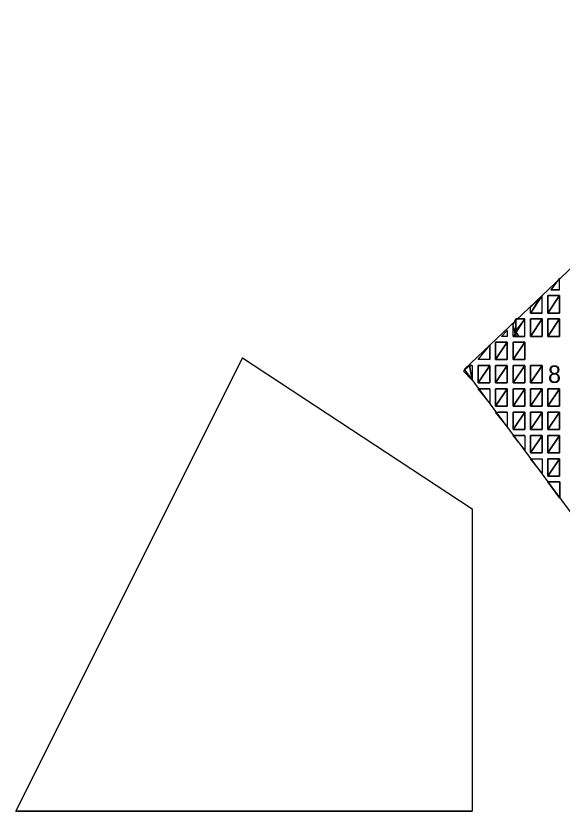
# Model space of a CAD drawing. Extents: x 0 to 34, y -1.2 to 22.
# Drawn here: x 2.909 to 3.443, y 4.123 to 4.9 of the extents above; entities that cross this region are included whole.
import ezdxf

# ---------------------------------------------------------------- set-up
doc = ezdxf.new("R2010")
doc.units = 0
doc.layers.add('Default', color=7, linetype='Continuous')

msp = doc.modelspace()

# ---------------------------------------------------------------- linework, layer by layer
at = {"layer": 'Default'}
for p, q in [((3.71021, 4.89963), (3.34713, 4.55419)), ((3.44033, 4.63213), (3.44033, 4.64351)), ((3.44033, 4.63213), (3.43179, 4.63213)), ((3.42326, 4.60937), (3.42326, 4.62644)), ((3.42895, 4.62644), (3.42895, 4.60937)), ((3.44033, 4.62644), (3.42895, 4.62644)), ((3.44033, 4.60937), (3.44033, 4.62644)), ((3.41188, 4.60937), (3.41188, 4.61506)), ((3.42326, 4.60937), (3.41188, 4.60937)), ((3.42895, 4.60937), (3.44033, 4.60937)), ((3.40619, 4.60368), (3.39765, 4.60368)), ((3.40619, 4.58661), (3.40619, 4.60368)), ((3.41188, 4.60368), (3.41188, 4.58661)), ((3.42326, 4.60368), (3.41188, 4.60368)), ((3.42326, 4.58661), (3.42326, 4.60368)), ((3.44033, 4.60368), (3.42895, 4.60368)), ((3.42895, 4.60368), (3.42895, 4.58661)), ((3.44033, 4.58661), (3.44033, 4.60368)), ((3.39481, 4.58661), (3.39481, 4.59799)), ((3.38912, 4.58661), (3.38342, 4.58661)), ((3.40619, 4.58661), (3.39481, 4.58661)), ((3.41188, 4.58661), (3.42326, 4.58661)), ((3.42895, 4.58661), (3.44033, 4.58661)), ((3.38912, 4.58092), (3.37773, 4.58092)), ((3.37773, 4.58092), (3.37773, 4.56385)), ((3.38912, 4.56385), (3.38912, 4.58092)), ((3.40619, 4.58092), (3.39481, 4.58092)), ((3.39481, 4.58092), (3.39481, 4.56385)), ((3.40619, 4.56385), (3.40619, 4.58092)), ((3.37204, 4.56385), (3.37204, 4.57523)), ((3.1305, 4.56547), (2.90919, 4.12284)), ((3.1305, 4.56547), (3.35479, 4.41798)), ((3.37204, 4.56385), (3.36066, 4.56385)), ((3.37773, 4.56385), (3.38912, 4.56385)), ((3.39481, 4.56385), (3.40619, 4.56385)), ((3.34772, 4.55371), (3.50785, 4.3379)), ((3.35497, 4.55816), (3.35213, 4.55816)), ((3.35497, 4.55816), (3.35497, 4.54393)), ((3.37204, 4.55816), (3.36066, 4.55816)), ((3.36066, 4.55816), (3.36066, 4.54109)), ((3.37204, 4.54109), (3.37204, 4.55816)), ((3.37773, 4.55816), (3.37773, 4.54109)), ((3.38912, 4.55816), (3.37773, 4.55816)), ((3.38912, 4.54109), (3.38912, 4.55816)), ((3.40619, 4.55816), (3.39481, 4.55816)), ((3.39481, 4.55816), (3.39481, 4.54109)), ((3.40619, 4.54109), (3.40619, 4.55816)), ((3.41188, 4.55816), (3.41188, 4.54109)), ((3.42326, 4.55816), (3.41188, 4.55816)), ((3.42326, 4.54109), (3.42326, 4.55816)), ((3.36066, 4.54109), (3.37204, 4.54109)), ((3.37773, 4.54109), (3.38912, 4.54109)), ((3.39481, 4.54109), (3.40619, 4.54109)), ((3.41188, 4.54109), (3.42326, 4.54109)), ((3.37204, 4.53539), (3.36066, 4.53539)), ((3.37204, 4.53539), (3.37204, 4.52117)), ((3.38912, 4.53539), (3.37773, 4.53539)), ((3.37773, 4.53539), (3.37773, 4.51832)), ((3.38912, 4.51832), (3.38912, 4.53539)), ((3.40619, 4.53539), (3.39481, 4.53539)), ((3.39481, 4.53539), (3.39481, 4.51832)), ((3.40619, 4.51832), (3.40619, 4.53539)), ((3.41188, 4.53539), (3.41188, 4.51832)), ((3.42326, 4.53539), (3.41188, 4.53539)), ((3.42326, 4.51832), (3.42326, 4.53539)), ((3.44033, 4.53539), (3.42895, 4.53539)), ((3.42895, 4.53539), (3.42895, 4.51832)), ((3.44033, 4.51832), (3.44033, 4.53539)), ((3.37773, 4.51832), (3.38912, 4.51832)), ((3.39481, 4.51832), (3.40619, 4.51832)), ((3.41188, 4.51832), (3.42326, 4.51832)), ((3.42895, 4.51832), (3.44033, 4.51832)), ((3.38912, 4.51263), (3.38058, 4.51263)), ((3.38912, 4.51263), (3.38912, 4.49841)), ((3.40619, 4.51263), (3.39481, 4.51263)), ((3.39481, 4.51263), (3.39481, 4.49556)), ((3.40619, 4.49556), (3.40619, 4.51263)), ((3.42326, 4.51263), (3.41188, 4.51263)), ((3.41188, 4.51263), (3.41188, 4.49556)), ((3.42326, 4.49556), (3.42326, 4.51263)), ((3.42895, 4.51263), (3.42895, 4.49556)), ((3.44033, 4.51263), (3.42895, 4.51263)), ((3.44033, 4.49556), (3.44033, 4.51263)), ((3.39481, 4.49556), (3.40619, 4.49556)), ((3.40619, 4.48987), (3.39481, 4.48987)), ((3.40619, 4.48987), (3.40619, 4.47565)), ((3.41188, 4.49556), (3.42326, 4.49556)), ((3.42326, 4.48987), (3.41188, 4.48987)), ((3.41188, 4.48987), (3.41188, 4.4728)), ((3.42326, 4.4728), (3.42326, 4.48987)), ((3.42895, 4.49556), (3.44033, 4.49556)), ((3.42895, 4.48987), (3.42895, 4.4728)), ((3.44033, 4.48987), (3.42895, 4.48987)), ((3.44033, 4.4728), (3.44033, 4.48987)), ((3.41188, 4.4728), (3.42326, 4.4728)), ((3.41188, 4.46711), (3.42326, 4.46711)), ((3.42326, 4.46711), (3.42326, 4.45288)), ((3.42895, 4.4728), (3.44033, 4.4728)), ((3.44033, 4.46711), (3.42895, 4.46711)), ((3.42895, 4.46711), (3.42895, 4.45004)), ((3.44033, 4.45004), (3.44033, 4.46711)), ((3.44033, 4.44435), (3.4288, 4.44435)), ((3.42895, 4.45004), (3.44033, 4.45004)), ((3.44033, 4.44435), (3.44033, 4.429)), ((3.35479, 4.41798), (3.35479, 4.12284)), ((2.90919, 4.12284), (3.35479, 4.12284))]:
    msp.add_line(p, q, dxfattribs=at)
for points in [[(3.43179, 4.63213), (3.44033, 4.63213), (3.44033, 4.64351)], [(3.41188, 4.60937), (3.42326, 4.60937), (3.42326, 4.62644)], [(3.41188, 4.60937), (3.41188, 4.61506), (3.42041, 4.6236)], [(3.42895, 4.60937), (3.42895, 4.62644), (3.44033, 4.62644)], [(3.44033, 4.62644), (3.44033, 4.60937), (3.42895, 4.60937)], [(3.44033, 4.62644), (3.44033, 4.62644), (3.44033, 4.62644)], [(3.39481, 4.58661), (3.40619, 4.58661), (3.40619, 4.60368)], [(3.39765, 4.58661), (3.39481, 4.59799), (3.39765, 4.60368)], [(3.39765, 4.60368), (3.40619, 4.60368), (3.39765, 4.5923)], [(3.41188, 4.58661), (3.41188, 4.60368), (3.42326, 4.60368)], [(3.42326, 4.60368), (3.42326, 4.58661), (3.41188, 4.58661)], [(3.42326, 4.60368), (3.42326, 4.60368), (3.42326, 4.60368)], [(3.44033, 4.60368), (3.44033, 4.58661), (3.42895, 4.58661)], [(3.42895, 4.58661), (3.42895, 4.60368), (3.44033, 4.60368)], [(3.44033, 4.60368), (3.44033, 4.60368), (3.44033, 4.60368)], [(3.38912, 4.58661), (3.38342, 4.58661), (3.38912, 4.5923)], [(3.39481, 4.58661), (3.39481, 4.59514), (3.4005, 4.58661)], [(3.36066, 4.56385), (3.37204, 4.57807), (3.37204, 4.56385)], [(3.38912, 4.58092), (3.38912, 4.56385), (3.37773, 4.56385)], [(3.37773, 4.56385), (3.37773, 4.58092), (3.38912, 4.58092)], [(3.38912, 4.58092), (3.38912, 4.58092), (3.38912, 4.58092)], [(3.39481, 4.56385), (3.39481, 4.58092), (3.40619, 4.58092)], [(3.40619, 4.58092), (3.40619, 4.56385), (3.39481, 4.56385)], [(3.40619, 4.58092), (3.40619, 4.58092), (3.40619, 4.58092)], [(3.1305, 4.56547), (3.35479, 4.41798), (3.35479, 4.12284), (2.90919, 4.12284)], [(3.35497, 4.54393), (3.34644, 4.55247), (3.35213, 4.55816)], [(3.35213, 4.55816), (3.35497, 4.55816), (3.35497, 4.54393)], [(3.37204, 4.55816), (3.37204, 4.54109), (3.36066, 4.54109)], [(3.36066, 4.54109), (3.36066, 4.55816), (3.37204, 4.55816)], [(3.37204, 4.55816), (3.37204, 4.55816), (3.37204, 4.55816)], [(3.37773, 4.54109), (3.37773, 4.55816), (3.38912, 4.55816)], [(3.38912, 4.55816), (3.38912, 4.54109), (3.37773, 4.54109)], [(3.38912, 4.55816), (3.38912, 4.55816), (3.38912, 4.55816)], [(3.40619, 4.55816), (3.40619, 4.54109), (3.39481, 4.54109)], [(3.39481, 4.54109), (3.39481, 4.55816), (3.40619, 4.55816)], [(3.40619, 4.55816), (3.40619, 4.55816), (3.40619, 4.55816)], [(3.41188, 4.54109), (3.41188, 4.55816), (3.42326, 4.55816)], [(3.42326, 4.55816), (3.42326, 4.54109), (3.41188, 4.54109)], [(3.42326, 4.55816), (3.42326, 4.55816), (3.42326, 4.55816)], [(3.36066, 4.53539), (3.37204, 4.53539), (3.37204, 4.52117)], [(3.38912, 4.53539), (3.38912, 4.51832), (3.37773, 4.51832)], [(3.37773, 4.51832), (3.37773, 4.53539), (3.38912, 4.53539)], [(3.38912, 4.53539), (3.38912, 4.53539), (3.38912, 4.53539)], [(3.39481, 4.51832), (3.39481, 4.53539), (3.40619, 4.53539)], [(3.40619, 4.53539), (3.40619, 4.51832), (3.39481, 4.51832)], [(3.40619, 4.53539), (3.40619, 4.53539), (3.40619, 4.53539)], [(3.41188, 4.51832), (3.41188, 4.53539), (3.42326, 4.53539)], [(3.42326, 4.53539), (3.42326, 4.51832), (3.41188, 4.51832)], [(3.42326, 4.53539), (3.42326, 4.53539), (3.42326, 4.53539)], [(3.44033, 4.53539), (3.44033, 4.51832), (3.42895, 4.51832)], [(3.42895, 4.51832), (3.42895, 4.53539), (3.44033, 4.53539)], [(3.44033, 4.53539), (3.44033, 4.53539), (3.44033, 4.53539)], [(3.37773, 4.51263), (3.38912, 4.51263), (3.38912, 4.49841)], [(3.39481, 4.49556), (3.39481, 4.51263), (3.40619, 4.51263)], [(3.40619, 4.51263), (3.40619, 4.49556), (3.39481, 4.49556)], [(3.40619, 4.51263), (3.40619, 4.51263), (3.40619, 4.51263)], [(3.42326, 4.51263), (3.42326, 4.49556), (3.41188, 4.49556)], [(3.41188, 4.49556), (3.41188, 4.51263), (3.42326, 4.51263)], [(3.42326, 4.51263), (3.42326, 4.51263), (3.42326, 4.51263)], [(3.42895, 4.49556), (3.42895, 4.51263), (3.44033, 4.51263)], [(3.44033, 4.51263), (3.44033, 4.49556), (3.42895, 4.49556)], [(3.44033, 4.51263), (3.44033, 4.51263), (3.44033, 4.51263)], [(3.39481, 4.48987), (3.40619, 4.48987), (3.40619, 4.47565)], [(3.40619, 4.48987), (3.40619, 4.48987), (3.40619, 4.48987)], [(3.42326, 4.48987), (3.42326, 4.4728), (3.41188, 4.4728)], [(3.41188, 4.4728), (3.41188, 4.48987), (3.42326, 4.48987)], [(3.42326, 4.48987), (3.42326, 4.48987), (3.42326, 4.48987)], [(3.42895, 4.4728), (3.42895, 4.48987), (3.44033, 4.48987)], [(3.44033, 4.48987), (3.44033, 4.4728), (3.42895, 4.4728)], [(3.44033, 4.48987), (3.44033, 4.48987), (3.44033, 4.48987)], [(3.41188, 4.46711), (3.42326, 4.46711), (3.42326, 4.45288)], [(3.44033, 4.46711), (3.44033, 4.45004), (3.42895, 4.45004)], [(3.42895, 4.45004), (3.42895, 4.46711), (3.44033, 4.46711)], [(3.44033, 4.46711), (3.44033, 4.46711), (3.44033, 4.46711)], [(3.44038, 4.42868), (3.4288, 4.44439), (3.44038, 4.44439)]]:
    msp.add_lwpolyline(points, close=True, dxfattribs=at)

# ---------------------------------------------------------------- texts
msp.add_text('8', height=0.01707, dxfattribs=at).set_placement((3.42895, 4.54109))

doc.saveas('drawing.dxf')
